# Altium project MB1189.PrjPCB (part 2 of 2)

## Sheet MCU.SchDoc: MCU
size A3; Date: 9/24/2014; Author: P.A.; CompanyName: STMicroelectronics; Organization: Microcontrollers Division; Address1: 12, Rue Jules HOROWITZ; Address2: 38019 Grenoble; Address3: FRANCE; DocumentNumber: MB1189; Revision: B-07; SheetNumber: 4; SheetTotal: 13; Project: STM32F469I-DISCO
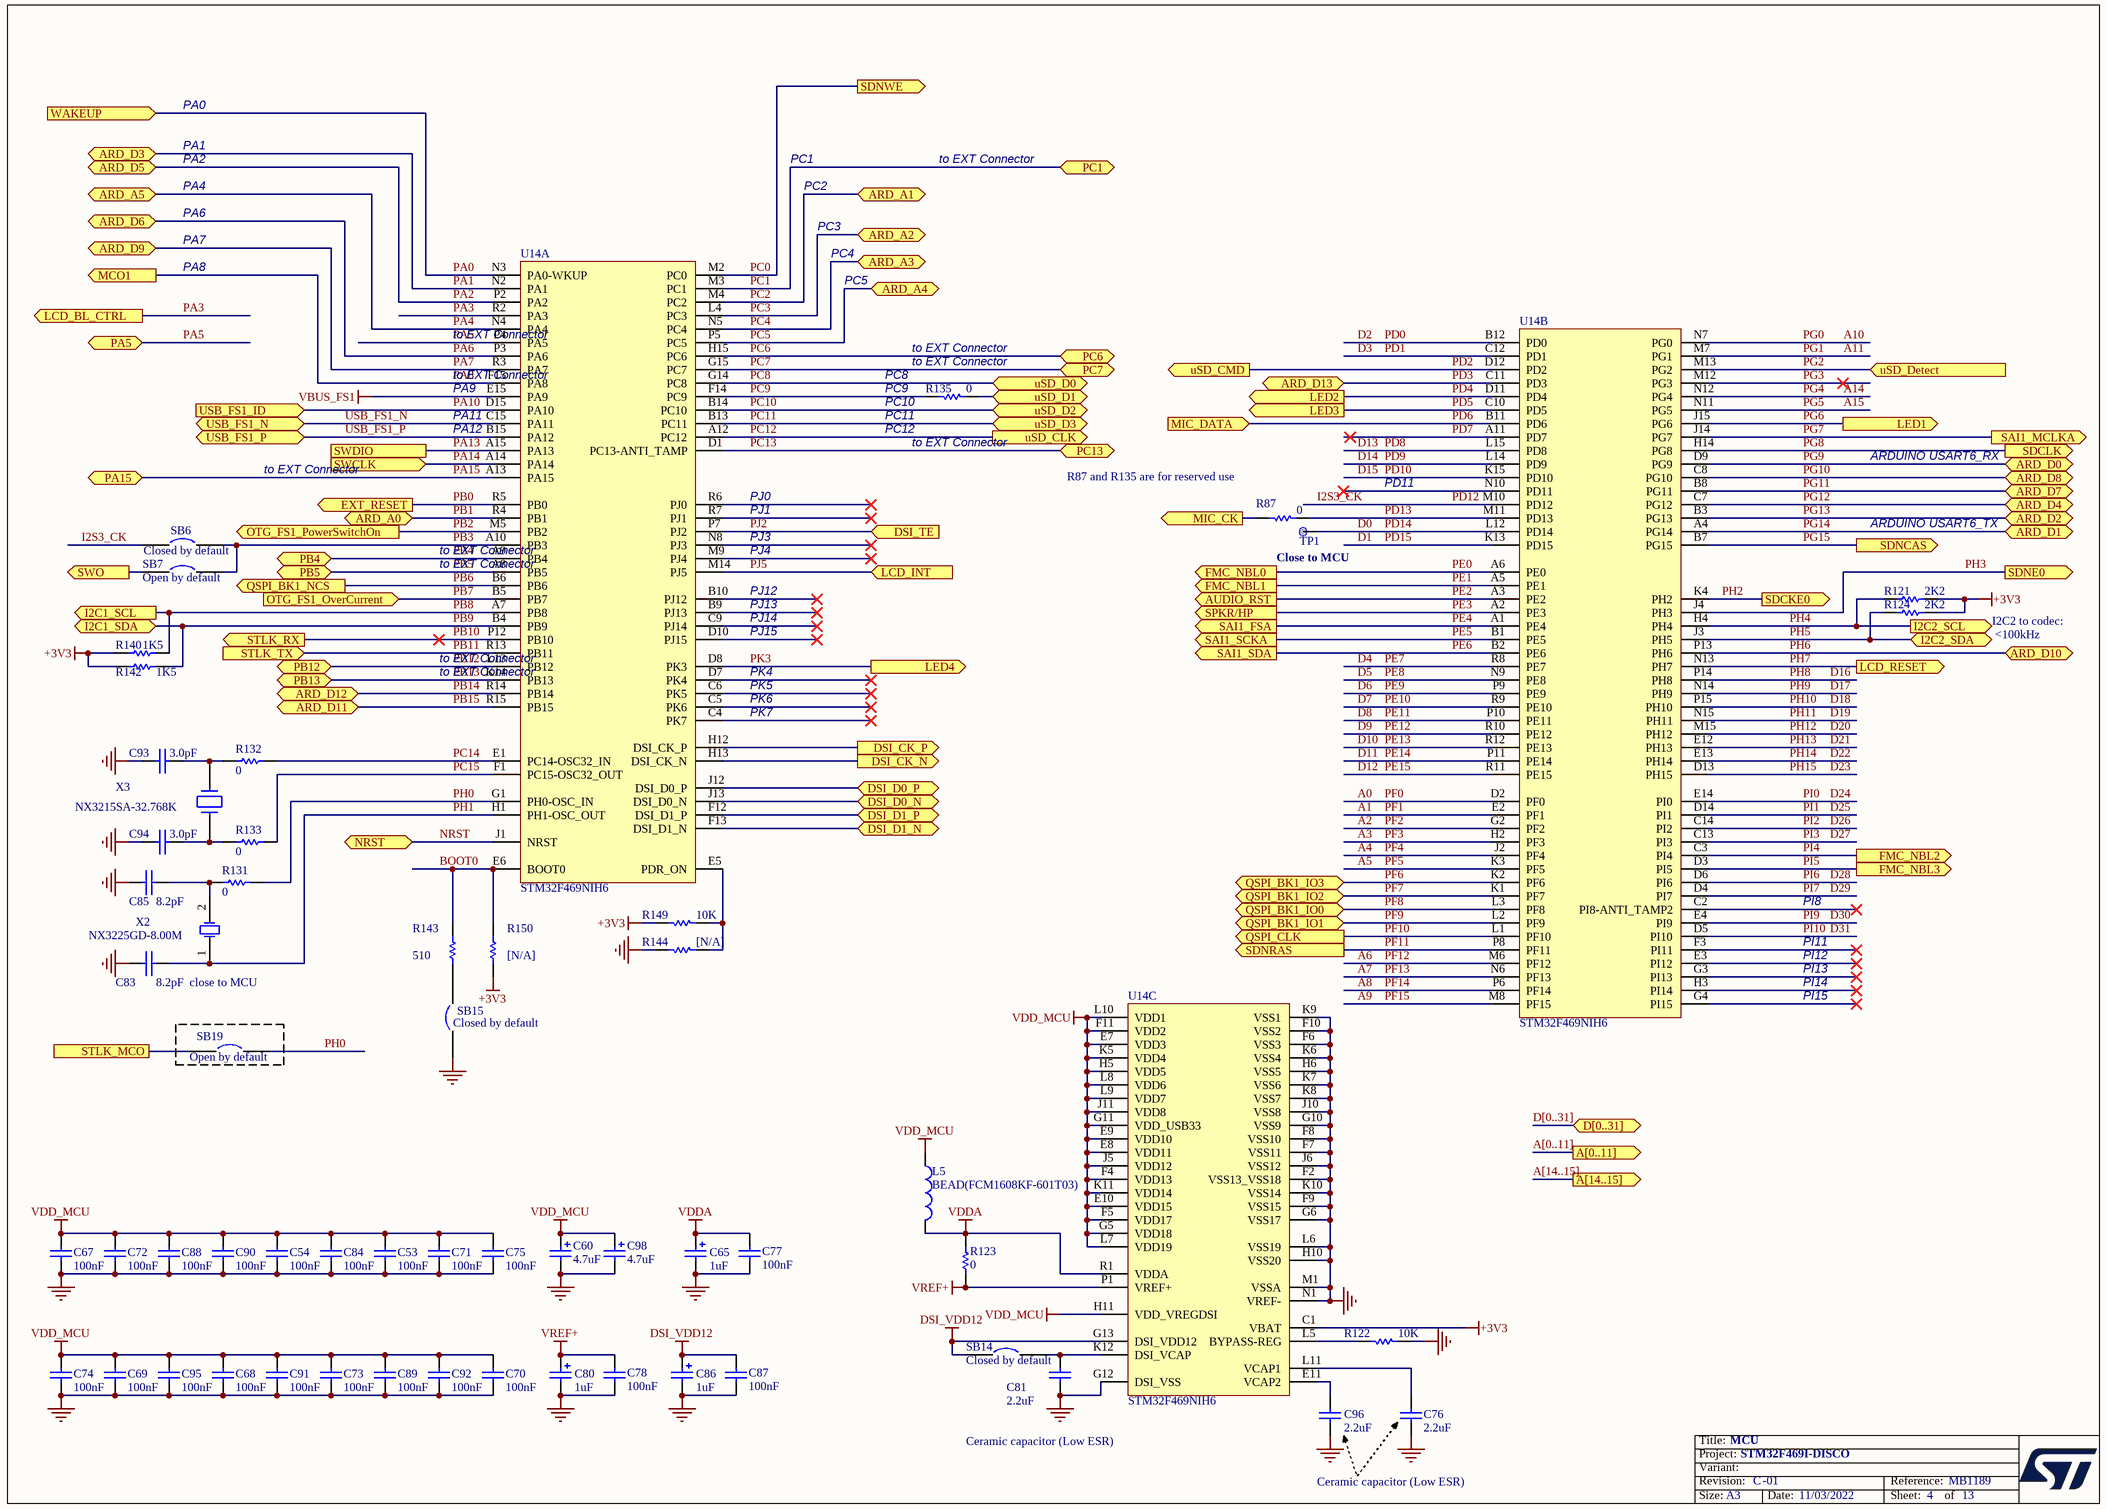
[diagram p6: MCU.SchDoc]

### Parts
C53  100nF  [0402C]
C54  100nF  [0402C]
C60  4.7uF  [CPOL_TAJ-A_1206_H180]
C65  1uF  [CPOL_TAJ-A_1206_H180]
C67  100nF  [0402C]
C68  100nF  [0402C]
C69  100nF  [0402C]
C70  100nF  [0402C]
C71  100nF  [0402C]
C72  100nF  [0402C]
C73  100nF  [0402C]
C74  100nF  [0402C]
C75  100nF  [0402C]
C76  2.2uF  [1206C]
C77  100nF  [0402C]
C78  100nF  [0402C]
C80  1uF  [CPOL_TAJ-A_1206_H180]
C81  2.2uF  [1206C]
C83  8.2pF  [0603C]
C84  100nF  [0402C]
C85  8.2pF  [0603C]
C86  1uF  [CPOL_TAJ-A_1206_H180]
C87  100nF  [0402C]
C88  100nF  [0402C]
C89  100nF  [0402C]
C90  100nF  [0402C]
C91  100nF  [0402C]
C92  100nF  [0402C]
C93  3.0pF  [0603C]
C94  3.0pF  [0603C]
C95  100nF  [0402C]
C96  2.2uF  [1206C]
C98  4.7uF  [CPOL_TAJ-A_1206_H180]
L5  BEAD(FCM1608KF-601T03)  [0603L]
R87  0  [0603R]
R121  2K2  [0603R]
R122  10K  [0402R]
R123  0  [0603R]
R124  2K2  [0603R]
R131  0  [0603R]
R132  0  [0603R]
R133  0  [0603R]
R135  0  [0603R]
R140  1K5  [0603R]
R142  1K5  [0603R]
R143  510  [0603R]
R144  [N/A]  [0603R]
R149  10K  [0402R]
R150  [N/A]  [0603R]
SB6  Closed by default  [SB_0603]
SB7  Open by default  [SB_0603]
SB14  Closed by default  [SB_0603]
SB15  Closed by default  [SB_0603]
SB19  Open by default  [SB_0603]
TP1  TP  [TP_C40]  (value not drawn)
U14  STM32F469NIH6  [BGA216_0R8_13X13]  (parts A,B,C of 3)
X2  NX3225GD-8.00M  [XTAL_2SM_3R2X2R5_H1]
X3  NX3215SA-32.768K  [XTAL_2SM_3R2X1R5]

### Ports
A[0..11] (out), A[14..15] (out), ARD_A0 (bidir), ARD_A1 (bidir), ARD_A2 (bidir), ARD_A3 (bidir), ARD_A4 (bidir), ARD_A5 (bidir), ARD_D0 (bidir), ARD_D1 (bidir), ARD_D2 (bidir), ARD_D3 (bidir), ARD_D4 (bidir), ARD_D5 (bidir), ARD_D6 (bidir), ARD_D7 (bidir), ARD_D8 (bidir), ARD_D9 (bidir), ARD_D10 (bidir), ARD_D11 (bidir), ARD_D12 (bidir), ARD_D13 (bidir), AUDIO_RST (out), D[0..31] (bidir), DSI_CK_N (out), DSI_CK_P (out), DSI_D0_N (bidir), DSI_D0_P (bidir), DSI_D1_N (bidir), DSI_D1_P (bidir), DSI_TE (in), EXT_RESET (out), FMC_NBL0 (out), FMC_NBL1 (out), FMC_NBL2 (out), FMC_NBL3 (out), I2C1_SCL (out), I2C1_SDA (bidir), I2C2_SCL (out), I2C2_SDA (bidir), LCD_BL_CTRL (out), LCD_INT (in), LCD_RESET (out), LED1 (out), LED2 (out), LED3 (out), LED4 (out), MCO1 (out), MIC_CK (out), MIC_DATA (in), NRST (bidir), OTG_FS1_OverCurrent (in), OTG_FS1_PowerSwitchOn (out), PA5 (bidir), PA15 (bidir), PB4 (bidir), PB5 (bidir), PB12 (bidir), PB13 (bidir), PC1 (bidir), PC6 (bidir), PC7 (bidir), PC13 (bidir), QSPI_BK1_IO0 (bidir), QSPI_BK1_IO1 (bidir), QSPI_BK1_IO2 (bidir), QSPI_BK1_IO3 (bidir), QSPI_BK1_NCS (out), QSPI_CLK (out), SAI1_FSA (out), SAI1_MCLKA (out), SAI1_SCKA (out), SAI1_SDA (out), SDCKE0 (out), SDCLK (out), SDNCAS (out), SDNE0 (out), SDNRAS (out), SDNWE (out), SPKR/HP (out), STLK_MCO, STLK_RX (out), STLK_TX (in), SWCLK (in), SWDIO, SWO (out), USB_FS1_ID (in), USB_FS1_N (bidir), USB_FS1_P (bidir), uSD_CLK (out), uSD_CMD (out), uSD_D0 (bidir), uSD_D1 (bidir), uSD_D2 (bidir), uSD_D3 (bidir), uSD_Detect (in), WAKEUP (in)

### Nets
+3V3: R121.1 R124.1 R140.1 R142.1 R149.2 R150.2 U14.C1(VBAT)
DSI_VDD12: C86.1 C87.2 SB14.1 U14.G13(DSI_VDD12)
GND: C53.2 C54.2 C60.2 C65.2 C67.2 C68.2 C69.2 C70.2 C71.2 C72.2 C73.2 C74.2 C75.2 C76.2 C77.1 C78.1 C80.2 C81.2 C83.2 C84.2 C85.2 C86.2 C87.1 C88.2 C89.2 C90.2 C91.2 C92.2 C93.2 C94.2 C95.2 C96.2 C98.2 R122.1 R144.2 SB15.1 U14.F2(VSS13_VSS18) U14.F6(VSS3) U14.F7(VSS11) U14.F8(VSS10) U14.F9(VSS15) U14.F10(VSS2) U14.G6(VSS17) U14.G10(VSS9) U14.G12(DSI_VSS) U14.H6(VSS5) U14.H10(VSS20) U14.J6(VSS12) U14.J10(VSS8) U14.K6(VSS4) U14.K7(VSS6) U14.K8(VSS7) U14.K9(VSS1) U14.K10(VSS14) U14.L6(VSS19) U14.M1(VSSA) U14.N1(VREF-)
VBUS_FS1: U14.E15(PA9)
VDD_MCU: C53.1 C54.1 C60.1 C67.1 C68.1 C69.1 C70.1 C71.1 C72.1 C73.1 C74.1 C75.1 C84.1 C88.1 C89.1 C90.1 C91.1 C92.1 C95.1 C98.1 L5.1 U14.E7(VDD3) U14.E8(VDD11) U14.E9(VDD10) U14.E10(VDD15) U14.F4(VDD13) U14.F5(VDD17) U14.F11(VDD2) U14.G5(VDD18) U14.G11(VDD_USB33) U14.H5(VDD5) U14.H11(VDD_VREGDSI) U14.J5(VDD12) U14.J11(VDD8) U14.K5(VDD4) U14.K11(VDD14) U14.L7(VDD19) U14.L8(VDD6) U14.L9(VDD7) U14.L10(VDD1)
VDDA: C65.1 C77.2 L5.2 R123.1 U14.R1(VDDA)
VREF+: C78.2 C80.1 R123.2 U14.P1(VREF+)
A0: U14.D2(PF0)  [also labelled PF0]
A1: U14.E2(PF1)  [also labelled PF1]
A2: U14.G2(PF2)  [also labelled PF2]
A3: U14.H2(PF3)  [also labelled PF3]
A4: U14.J2(PF4)  [also labelled PF4]
A5: U14.K3(PF5)  [also labelled PF5]
A6: U14.M6(PF12)  [also labelled PF12]
A7: U14.N6(PF13)  [also labelled PF13]
A8: U14.P6(PF14)  [also labelled PF14]
A9: U14.M8(PF15)  [also labelled PF15]
A10: U14.N7(PG0)  [also labelled PG0]
A11: U14.M7(PG1)  [also labelled PG1]
A14: U14.N12(PG4)  [also labelled PG4]
A15: U14.N11(PG5)  [also labelled PG5]
BOOT0: R143.1 R150.1 U14.E6(BOOT0)
D0: TP1.1 U14.L12(PD14)  [also labelled PD14]
D1: U14.K13(PD15)  [also labelled PD15]
D2: U14.B12(PD0)  [also labelled PD0]
D3: U14.C12(PD1)  [also labelled PD1]
D4: U14.R8(PE7)  [also labelled PE7]
D5: U14.N9(PE8)  [also labelled PE8]
D6: U14.P9(PE9)  [also labelled PE9]
D7: U14.R9(PE10)  [also labelled PE10]
D8: U14.P10(PE11)  [also labelled PE11]
D9: U14.R10(PE12)  [also labelled PE12]
D10: U14.R12(PE13)  [also labelled PE13]
D11: U14.P11(PE14)  [also labelled PE14]
D12: U14.R11(PE15)  [also labelled PE15]
D13: U14.L15(PD8)  [also labelled PD8]
D14: U14.L14(PD9)  [also labelled PD9]
D15: U14.K15(PD10)  [also labelled PD10]
D16: U14.P14(PH8)  [also labelled PH8]
D17: U14.N14(PH9)  [also labelled PH9]
D18: U14.P15(PH10)  [also labelled PH10]
D19: U14.N15(PH11)  [also labelled PH11]
D20: U14.M15(PH12)  [also labelled PH12]
D21: U14.E12(PH13)  [also labelled PH13]
D22: U14.E13(PH14)  [also labelled PH14]
D23: U14.D13(PH15)  [also labelled PH15]
D24: U14.E14(PI0)  [also labelled PI0]
D25: U14.D14(PI1)  [also labelled PI1]
D26: U14.C14(PI2)  [also labelled PI2]
D27: U14.C13(PI3)  [also labelled PI3]
D28: U14.D6(PI6)  [also labelled PI6]
D29: U14.D4(PI7)  [also labelled PI7]
D30: U14.E4(PI9)  [also labelled PI9]
D31: U14.D5(PI10)  [also labelled PI10]
HSSI_CLK_N: U14.H13(DSI_CK_N) ; port DSI_CK_N
HSSI_CLK_P: U14.H12(DSI_CK_P) ; port DSI_CK_P
HSSI_D0_N: U14.J13(DSI_D0_N) ; port DSI_D0_N
HSSI_D0_P: U14.J12(DSI_D0_P) ; port DSI_D0_P
HSSI_D1_N: U14.F13(DSI_D1_N) ; port DSI_D1_N
HSSI_D1_P: U14.F12(DSI_D1_P) ; port DSI_D1_P
I2S3_CK: SB6.1 U14.M10(PD12)  [also labelled PD12]
MIC_CK: R87.1 ; port MIC_CK
NRST: U14.J1(NRST) ; port NRST
PA0: U14.N3(PA0-WKUP) ; port WAKEUP
PA1: U14.N2(PA1) ; port ARD_D3
PA2: U14.P2(PA2) ; port ARD_D5
PA3: U14.R2(PA3) ; port LCD_BL_CTRL  [project net LCD_BL_CTRL]
PA4: U14.N4(PA4) ; port ARD_A5
PA5: U14.P4(PA5) ; port PA5
PA6: U14.P3(PA6) ; port ARD_D6
PA7: U14.R3(PA7) ; port ARD_D9
PA8: U14.F15(PA8) ; port MCO1
PA10: U14.D15(PA10) ; port USB_FS1_ID
PA13: U14.A15(PA13) ; port SWDIO
PA14: U14.A14(PA14) ; port SWCLK
PA15: U14.A13(PA15) ; port PA15
PB0: U14.R5(PB0) ; port EXT_RESET
PB1: U14.R4(PB1) ; port ARD_A0
PB2: U14.M5(PB2) ; port OTG_FS1_PowerSwitchOn
PB3: SB6.2 SB7.2 U14.A10(PB3)
PB4: U14.A9(PB4) ; port PB4
PB5: U14.A8(PB5) ; port PB5
PB6: U14.B6(PB6) ; port QSPI_BK1_NCS
PB7: U14.B5(PB7) ; port OTG_FS1_OverCurrent
PB8: R140.2 U14.A7(PB8) ; port I2C1_SCL  [project net I2C1_SCL]
PB9: R142.2 U14.B4(PB9) ; port I2C1_SDA  [project net I2C1_SDA]
PB10: U14.P12(PB10) ; port STLK_RX
PB11: U14.R13(PB11) ; port STLK_TX
PB12: U14.L13(PB12) ; port PB12
PB13: U14.K14(PB13) ; port PB13
PB14: U14.R14(PB14) ; port ARD_D12
PB15: U14.R15(PB15) ; port ARD_D11
PC0: U14.M2(PC0) ; port SDNWE
PC1: U14.M3(PC1) ; port PC1
PC2: U14.M4(PC2) ; port ARD_A1
PC3: U14.L4(PC3) ; port ARD_A2
PC4: U14.N5(PC4) ; port ARD_A3
PC5: U14.P5(PC5) ; port ARD_A4
PC6: U14.H15(PC6) ; port PC6
PC7: U14.G15(PC7) ; port PC7
PC8: U14.G14(PC8) ; port uSD_D0
PC9: R135.1 U14.F14(PC9)
PC10: U14.B14(PC10) ; port uSD_D2
PC11: U14.B13(PC11) ; port uSD_D3
PC12: U14.A12(PC12) ; port uSD_CLK
PC13: U14.D1(PC13-ANTI_TAMP) ; port PC13
PC14: R132.2 U14.E1(PC14-OSC32_IN)
PC15: R133.2 U14.F1(PC15-OSC32_OUT)
PD2: U14.D12(PD2) ; port uSD_CMD
PD3: U14.C11(PD3) ; port ARD_D13
PD4: U14.D11(PD4) ; port LED2
PD5: U14.C10(PD5) ; port LED3
PD6: U14.B11(PD6) ; port MIC_DATA
PD7: U14.A11(PD7)
PD13: R87.2 U14.M11(PD13)
PE0: U14.A6(PE0) ; port FMC_NBL0
PE1: U14.A5(PE1) ; port FMC_NBL1
PE2: U14.A3(PE2) ; port AUDIO_RST  [project net AUDIO_RST]
PE3: U14.A2(PE3) ; port SPKR/HP
PE4: U14.A1(PE4) ; port SAI1_FSA
PE5: U14.B1(PE5) ; port SAI1_SCKA
PE6: U14.B2(PE6) ; port SAI1_SDA
PF6: U14.K2(PF6) ; port QSPI_BK1_IO3
PF7: U14.K1(PF7) ; port QSPI_BK1_IO2
PF8: U14.L3(PF8) ; port QSPI_BK1_IO0
PF9: U14.L2(PF9) ; port QSPI_BK1_IO1
PF10: U14.L1(PF10) ; port QSPI_CLK
PF11: U14.P8(PF11) ; port SDNRAS
PG2: U14.M13(PG2) ; port uSD_Detect
PG3: U14.M12(PG3)
PG6: U14.J15(PG6) ; port LED1
PG7: U14.J14(PG7) ; port SAI1_MCLKA
PG8: U14.H14(PG8) ; port SDCLK
PG9: U14.D9(PG9) ; port ARD_D0
PG10: U14.C8(PG10) ; port ARD_D8
PG11: U14.B8(PG11) ; port ARD_D7
PG12: U14.C7(PG12) ; port ARD_D4
PG13: U14.B3(PG13) ; port ARD_D2
PG14: U14.A4(PG14) ; port ARD_D1
PG15: U14.B7(PG15) ; port SDNCAS
PH0: R131.1 SB19.2 U14.G1(PH0-OSC_IN)
PH1: C83.1 U14.H1(PH1-OSC_OUT) X2.1(OSC1)
PH2: U14.K4(PH2) ; port SDCKE0
PH3: U14.J4(PH3) ; port SDNE0
PH4: R121.2 U14.H4(PH4) ; port I2C2_SCL  [project net I2C2_SCL]
PH5: R124.2 U14.J3(PH5) ; port I2C2_SDA  [project net I2C2_SDA]
PH6: U14.P13(PH6) ; port ARD_D10
PH7: U14.N13(PH7) ; port LCD_RESET  [project net LCD_RST]
PI4: U14.C3(PI4) ; port FMC_NBL2
PI5: U14.D3(PI5) ; port FMC_NBL3
PJ2: U14.P7(PJ2) ; port DSI_TE
PJ5: U14.M14(PJ5) ; port LCD_INT  [project net LCD_INT]
PK3: U14.D8(PK3) ; port LED4
STLK_MCO: SB19.1 ; port STLK_MCO
SWO: SB7.1 ; port SWO
USB_FS1_N: U14.C15(PA11) ; port USB_FS1_N
USB_FS1_P: U14.B15(PA12) ; port USB_FS1_P
uSD_D1: R135.2 ; port uSD_D1
NetC76_1: C76.1 U14.L11(VCAP1)
NetC81_1: C81.1 SB14.2 U14.K12(DSI_VCAP)
NetC85_1: C85.1 R131.2 X2.2(OSC2)
NetC93_1: C93.1 R132.1 X3.1
NetC94_1: C94.1 R133.1 X3.2
NetC96_1: C96.1 U14.E11(VCAP2)
NetR122_2: R122.2 U14.L5(BYPASS-REG)
NetR143_2: R143.2 SB15.2
NetR144_1: R144.1 R149.1 U14.E5(PDR_ON)

Not connected (* = marked no-connect by the designer): U14 B9(PJ13)* B10(PJ12)* C2(PI8-ANTI_TAMP2)* C4(PK7)* C5(PK6)* C6(PK5)* C9(PJ14)* D7(PK4)* D10(PJ15)* E3(PI12)* F3(PI11)* G3(PI13)* G4(PI15)* H3(PI14)* M9(PJ4)* N8(PJ3)* N10(PD11)* R6(PJ0)* R7(PJ1)*

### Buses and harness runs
bus A[0..11] = port A[0..11]
bus A[14..15] = port A[14..15]
bus D[0..31] = port D[0..31]

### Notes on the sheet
- PA0
- PA1
- PA2
- PC1
- to EXT Connector
- PA6
- PA7
- PA4
- PC2
- PC3
- PA8
- PC4
- PC5
- (near R135) PC8
- (near R135) to EXT Connector
- (near U14) PA11
- (near U14) PA12
- (near U14) PA9
- (near R135) PC9
- (near R135) PC10
- (near R135) PC11
- (near R135) PC12
- PJ1
- PJ0
- (near R87) R87 and R135 are for reserved use
- PD11
- ARDUINO USART6_RX
- PJ4
- PJ3
- Close to MCU
- ARDUINO USART6_TX
- PJ15
- PJ13
- PJ12
- PJ14
- I2C2 to codec:
  <100kHz
- PK7
- PK6
- PK5
- PK4
- PI8
- close to MCU
- PI14
- PI13
- PI12
- PI11
- PI15
- Ceramic capacitor (Low ESR)

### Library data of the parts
C53 C67-C75 C84 C88-C92 C95 = CAP: Capacitor; Manuf_part_1: CC0402KRX7R7BB104; Manuf_1: YAGEO; Ordered by: Subcon
C54 = CAP: Capacitor; Manuf_Part_1: CC0402KRX7R7BB104; Manuf_1: YAGEO; Ordered by: Subcon
C60 C98 = Cap_TAJA475K016R: Capacitor, Tantalum, 4.7uF, 16V, 10%, 4ohms, pkg Type_A (3216 metric), T=1.6mm; Manuf_1: AVX; Value: 4.7uF 16V
C65 C80 C86 = Cap_TAJA105K016RNJ: Capacitor, Tantalum, 1uF, 16V, 10%, 11Ohms, pkg Type_A (3216 metric), T=1.6mm; Manuf_1: AVX; Value: 1uF (16V)
C76 = Cap: Capacitor; Manuf_1: YAGEO; Manuf_part_1: CC1206KKX7R7BB225; Ordered by: Subcon
C77 C78 C87 = Cap: Capacitor; Manuf_part_1: CC0402KRX7R7BB104; Manuf_1: YAGEO; Ordered by: Subcon
C81 C96 = Cap: Capacitor; Manuf_part_1: CC1206KKX7R7BB225; Manuf_1: YAGEO; Ordered by: Subcon
C83 C85 = CAP: Capacitor; Manuf_part_1: CC0603CRNPO9BN8R2; Manuf_1: YAGEO; Ordered by: Subcon
C93 C94 = CAP: Capacitor; Manuf_1: YAGEO; Manuf_part_1: CC0603CRNPO9BN3R0; Ordered by: Subcon
L5 = Inductor: Manuf_1: Tai-Tech Advanced Electronics; Manuf_part_1: FCM1608KF-601T05; Value: 100uH; Ordered by: Subcon
R87 R123 R131-R133 R135 = Res1: Resistor; Manuf_1: YAGEO; Manuf_part_1: RC0603JR-070RL; Ordered by: Subcon
R121 R124 = Res1: Resistor; Manuf_1: YAGEO; Manuf_part_1: RC0603FR-072K2L; Ordered by: Subcon
R122 R149 = Res1: Resistor; Manuf_1: YAGEO; Manuf_part_1: RC0402FR-0710KL; Ordered by: Subcon
R140 R142 = Res1: Resistor; Manuf_1: YAGEO; Manuf_part_1: RC0603FR-071K5L; Ordered by: Subcon
R143 = res1: Resistor; Manuf_1: YAGEO; Manuf_part_1: RC0603FR-07510RL; Ordered by: Subcon
R144 = Res1: Resistor; Value: 1K; Ordered by: Subcon; Fitted: NO
R150 = res1: Resistor; Value: 1K; Ordered by: Subcon; Fitted: NO
SB6 SB14 SB15 = Circuit Breaker: Ordered by: Subcon; Comments: Solder bridge
SB7 SB19 = Circuit Breaker: Ordered by: Subcon; Comments: Solder bridge; Solder: NO
TP1 = TP: Ordered by: Subcon
U14 = Manta_Dragon_TFBGA216: Manuf_Part_1: STM32F469NIH6U cut 1.0; Ordered by: ST; Ref St: 9175177; ECCN_US/EU: 3A991A2/NEC
X2 = XTAL_8M_NX3225GD: Crystal 8Mhz, 8pF, -+50PPM, SMD; Manuf_1: NDK; Manuf_Part_1: NX3225GD 8MHz EXS00A-CG04874; Manuf_Part_2: NX3225GD-8.000M-STD-CRA-3; ECCN_US/EU: EAR99/NEC; NDK Ref: X3127326; Ref St: 9157029; Provided: ST
X3 = XTAL_32K_NX3215SA: Crystal 32.768kHz, 6pF, -+20PPM, R=50K, SMD; Manuf_1: NDK; Manuf_Part_1: NX3215SA 32.768KHz EXS00A-MU00525; ECCN_US/EU: EAR99/NEC; Ref St: 9157034; NDK Ref: X3101802; Provided: ST

## Sheet Arduino_ Connectors.SchDoc: Arduino Uno connector
size A4; Date: 9/24/2014; Author: P.A.; CompanyName: STMicroelectronics; Organization: Microcontrollers Division; Address1: 12, Rue Jules HOROWITZ; Address2: 38019 Grenoble; Address3: FRANCE; DocumentNumber: MB1189; Revision: B-07; SheetNumber: 12; SheetTotal: 13; Project: STM32F469I-DISCO
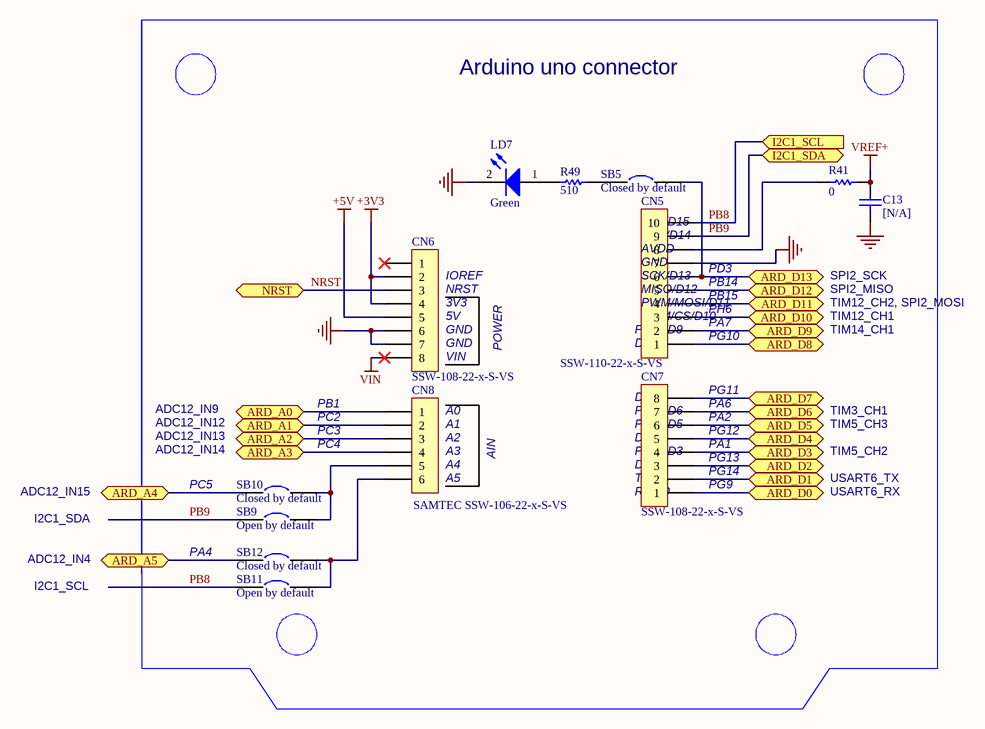
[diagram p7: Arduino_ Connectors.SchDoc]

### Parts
C13  [N/A]  [0603C]
CN5  SSW-110-22-x-S-VS  [SSW-110-22-X-S-VS]
CN6  SSW-108-22-x-S-VS  [SSW-108-22-X-S-VS]
CN7  SSW-108-22-x-S-VS  [SSW-108-22-X-S-VS]
CN8  SAMTEC SSW-106-22-x-S-VS  [SSW-106-22-X-S-VS]
LD7  Green  [0603D]
R41  0  [0603R]
R49  510  [0603R]
SB5  Closed by default  [SB_0603]
SB9  Open by default  [SB_0603]
SB10  Closed by default  [SB_0603]
SB11  Open by default  [SB_0603]
SB12  Closed by default  [SB_0603]

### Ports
ARD_A0 (bidir), ARD_A1 (bidir), ARD_A2 (bidir), ARD_A3 (bidir), ARD_A4 (bidir), ARD_A5 (bidir), ARD_D0 (bidir), ARD_D1 (bidir), ARD_D2 (bidir), ARD_D3 (bidir), ARD_D4 (bidir), ARD_D5 (bidir), ARD_D6 (bidir), ARD_D7 (bidir), ARD_D8 (bidir), ARD_D9 (bidir), ARD_D10 (bidir), ARD_D11 (bidir), ARD_D12 (bidir), ARD_D13 (bidir), I2C1_SCL (in), I2C1_SDA (bidir), NRST (bidir)

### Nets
+3V3: CN6.2 CN6.4
+5V: CN6.5
GND: C13.1 CN5.7 CN6.6 CN6.7 LD7.2(K)
VIN: CN6.8
VREF+: C13.2 R41.1
NRST: CN6.3 ; port NRST
PA1: CN7.4 ; port ARD_D3
PA2: CN7.6 ; port ARD_D5
PA4: SB12.1 ; port ARD_A5
PA6: CN7.7 ; port ARD_D6
PA7: CN5.2 ; port ARD_D9
PB1: CN8.1 ; port ARD_A0
PB8: CN5.10 SB11.1 ; port I2C1_SCL  [project net I2C1_SCL]
PB9: CN5.9 SB9.1 ; port I2C1_SDA  [project net I2C1_SDA]
PB14: CN5.5 ; port ARD_D12
PB15: CN5.4 ; port ARD_D11
PC2: CN8.2 ; port ARD_A1
PC3: CN8.3 ; port ARD_A2
PC4: CN8.4 ; port ARD_A3
PC5: SB10.1 ; port ARD_A4
PD3: CN5.6 SB5.2 ; port ARD_D13
PG9: CN7.1 ; port ARD_D0
PG10: CN5.1 ; port ARD_D8
PG11: CN7.8 ; port ARD_D7
PG12: CN7.5 ; port ARD_D4
PG13: CN7.3 ; port ARD_D2
PG14: CN7.2 ; port ARD_D1
PH6: CN5.3 ; port ARD_D10
NetCN5_8: CN5.8 R41.2
NetCN8_5: CN8.5 SB9.2 SB10.2
NetCN8_6: CN8.6 SB11.2 SB12.2
NetLD7_1: LD7.1(A) R49.2
NetR49_1: R49.1 SB5.1

Not connected (* = marked no-connect by the designer): CN6 1*

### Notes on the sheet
- Arduino uno connector
- (near CN5) SDA/D14
- SCL/D15
- (near CN5) AVDD
- (near CN6) IOREF
- (near CN6) NRST
- (near CN6) 3V3
- (near CN5) SCK/D13
- (near CN5) MISO/D12
- (near CN5) PWM/MOSI/D11
- (near CN5) GND
- (near CN5) PH6
- (near CN5) PB15
- (near CN5) PB14
- (near CN5) PD3
- TIM12_CH2, SPI2_MOSI
- SPI2_MISO
- SPI2_SCK
- (near CN6) 5V
- (near CN6) GND
- (near CN6) VIN
- POWER
- (near CN5) D8
- (near CN5) PWM/D9
- (near CN5) PWM/CS/D10
- (near CN5) PG10
- (near CN5) PA7
- TIM14_CH1
- TIM12_CH1
- ADC12_IN14
- ADC12_IN13
- ADC12_IN12
- ADC12_IN9
- PB1
- PC2
- PC3
- PC4
- (near CN8) A0
- (near CN8) A1
- (near CN8) A2
- (near CN7) D4
- (near CN7) PWM/D5
- (near CN7) PWM/D6
- (near CN7) D7
- (near CN7) PA1
- (near CN7) PG12
- (near CN7) PA2
- (near CN7) PA6
- PG11
- TIM5_CH3
- TIM3_CH1
- ADC12_IN15
- I2C1_SDA
- PC5
- (near CN8) A3
- (near CN8) A4
- (near CN8) A5
- AIN
- (near CN7) RX/D0
- (near CN7) TX/D1
- (near CN7) D2
- (near CN7) PWM/D3
- (near CN7) PG9
- (near CN7) PG14
- (near CN7) PG13
- USART6_RX
- USART6_TX
- TIM5_CH2
- ADC12_IN4
- PA4
- I2C1_SCL

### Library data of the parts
C13 = Cap: Capacitor; Value: 10nF; Ordered by: Subcon; Fitted: NO
CN5 = Header 10X1_Female: Header, 10-Pin, Single row,female; Manuf_1: SAMTEC; Ordered by: Subcon; Silkscreen: pin names as in schematic
CN6 CN7 = Header 8X1_Female: Header, 8-Pin, Single row,female; Manuf_1: SAMTEC; Ordered by: Subcon; Silkscreen: pin names as in schematic
CN8 = Header 6X1_Female: Header, 6-Pin, Single row,female SMD; Ordered by: Subcon; Silkscreen: pin names as in schematic
LD7 = LED2: Typical RED, GREEN, YELLOW, AMBER GaAs LED; Manuf_1: Everlight Electronics; Manuf_part_1: 19-217/G7C-AN1P2/3T; Ordered by: Subcon; ECCN_US/EU: EAR99/NEC
R41 = Res1: as R87 on sheet MCU
R49 = Res1: Resistor; Manuf_1: YAGEO; Manuf_part_1: RC0603FR-07510RL; Ordered by: Subcon
SB5 SB10 SB12 = Circuit Breaker: as SB6 on sheet MCU
SB9 SB11 = Circuit Breaker: as SB7 on sheet MCU

## Sheet DSI_LCD.SchDoc: 4 inch DSI LCD board
size A4; Date: 9/24/2014; Author: P.A.; CompanyName: STMicroelectronics; Organization: Microcontrollers Division; Address1: 12, Rue Jules HOROWITZ; Address2: 38019 Grenoble; Address3: FRANCE; DocumentNumber: MB1189; Revision: B-07; SheetNumber: 7; SheetTotal: 13; Project: STM32F469I-DISCO
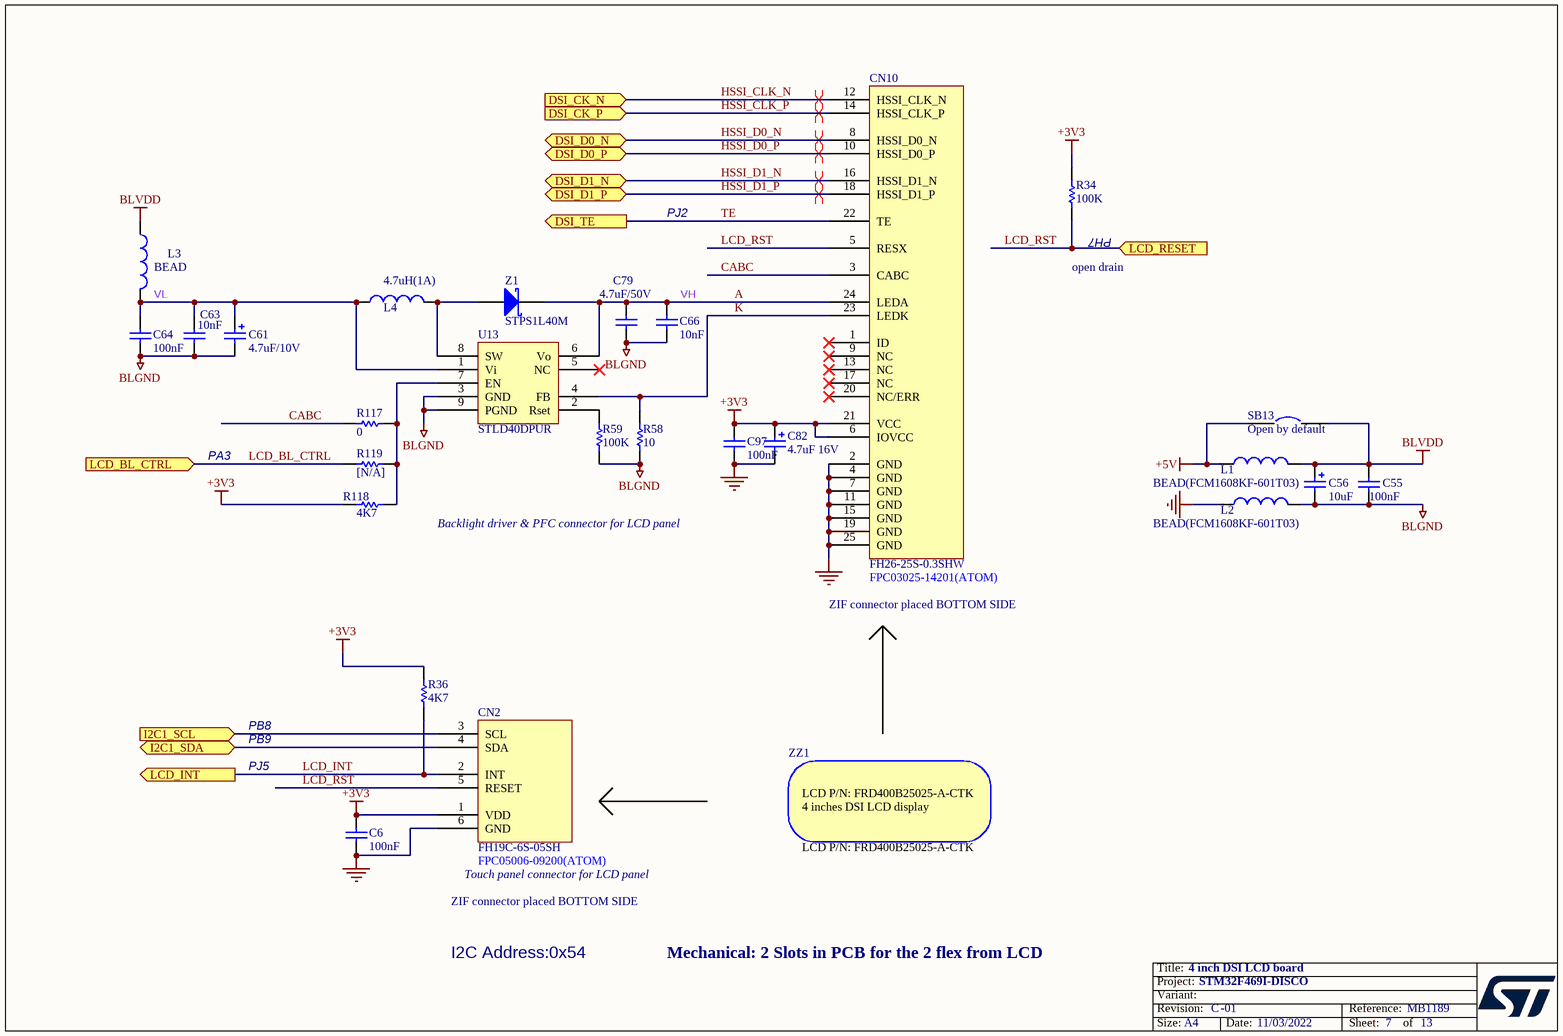
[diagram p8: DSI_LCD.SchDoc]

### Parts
C6  100nF  [0402C]
C55  100nF  [0402C]
C56  10uF  [CPOL_TAJ-A_1206_H180]
C61  4.7uF/10V  [1206C]
C63  10nF  [0603C]
C64  100nF  [0402C]
C66  10nF  [0603C]
C79  4.7uF/50V  [1206C]
C82  4.7uF 16V  [CPOL_TAJ-A_1206_H180]
C97  100nF  [0402C]
CN2  FH19C-6S-05SH  [FH19C-6S-0R5SH_FPC_CPT]
CN10  FH26-25S-0.3SHW  [FPC25_FPC03025-1420]
L1  BEAD(FCM1608KF-601T03)  [0603L]
L2  BEAD(FCM1608KF-601T03)  [0603L]
L3  BEAD  [0603L]
L4  4.7uH(1A)  [1210L]
R34  100K  [0402R]
R36  4K7  [0603R]
R58  10  [0603R]
R59  100K  [0603R]
R117  0  [0603R]
R118  4K7  [0603R]
R119  [N/A]  [0603R]
SB13  Open by default  [SB_0603]
U13  STLD40DPUR  [SON8_0R65_3X3]
Z1  STPS1L40M  [DO-216AA]
ZZ1  LCD P/N: FRD400B25025-A-CTK  [toto]  (mechanical)

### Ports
DSI_CK_N (in), DSI_CK_P (in), DSI_D0_N (bidir), DSI_D0_P (bidir), DSI_D1_N (bidir), DSI_D1_P (bidir), DSI_TE (out), I2C1_SCL (in), I2C1_SDA (bidir), LCD_BL_CTRL (in), LCD_INT (out), LCD_RESET (in)

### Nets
+3V3: C6.2 C82.1 C97.2 CN2.1(VDD) CN10.6(IOVCC) CN10.21(VCC) R34.1 R36.1 R118.2
+5V: L1.1 SB13.1
BLGND: C55.2 C56.2 C61.2 C63.1 C64.1 C66.1 C79.2 L2.2 R58.1 R59.2 U13.3(GND) U13.9(PGND)
BLVDD: C55.1 C56.1 L1.2 L3.1 SB13.2
GND: C6.1 C82.2 C97.1 CN2.6(GND) CN10.2(GND) CN10.4(GND) CN10.7(GND) CN10.11(GND) CN10.15(GND) CN10.19(GND) CN10.25(GND) L2.1
A: C66.2 C79.1 CN10.24(LEDA) U13.6(Vo) Z1.2(K)  [also labelled VH]
CABC: CN10.3(CABC) R117.2
HSSI_CLK_N: CN10.12(HSSI_CLK_N) ; port DSI_CK_N
HSSI_CLK_P: CN10.14(HSSI_CLK_P) ; port DSI_CK_P
HSSI_D0_N: CN10.8(HSSI_D0_N) ; port DSI_D0_N
HSSI_D0_P: CN10.10(HSSI_D0_P) ; port DSI_D0_P
HSSI_D1_N: CN10.16(HSSI_D1_N) ; port DSI_D1_N
HSSI_D1_P: CN10.18(HSSI_D1_P) ; port DSI_D1_P
I2C1_SCL: CN2.3(SCL) ; port I2C1_SCL
I2C1_SDA: CN2.4(SDA) ; port I2C1_SDA
K: CN10.23(LEDK) R58.2 U13.4(FB)
LCD_BL_CTRL: R119.2 ; port LCD_BL_CTRL
LCD_INT: CN2.2(INT) R36.2 ; port LCD_INT
LCD_RST: CN2.5(RESET) CN10.5(RESX) R34.2 ; port LCD_RESET
TE: CN10.22(TE) ; port DSI_TE  [project net PJ2]
VL: C61.1 C63.2 C64.2 L3.2 L4.1 U13.1(Vi)
NetL4_2: L4.2 U13.8(SW) Z1.1(A)
NetR59_1: R59.1 U13.2(Rset)
NetR117_1: R117.1 R118.1 R119.1 U13.7(EN)

Not connected (* = marked no-connect by the designer): CN10 1(ID)* 9(NC)* 13(NC)* 17(NC)* 20(NC/ERR)*; U13 5(NC)*

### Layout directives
differential pair: HSSI_CLK_N, HSSI_CLK_P, HSSI_D0_N, HSSI_D0_P, HSSI_D1_N, HSSI_D1_P

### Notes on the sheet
- PJ2
- (near R34) PH7
- open drain
- PA3
- Backlight driver & PFC connector for LCD panel
- (near CN10) FPC03025-14201(ATOM)
- ZIF connector placed BOTTOM SIDE
- PB9
- PB8
- PJ5
- (near CN2) Touch panel connector for LCD panel
- (near CN2) FPC05006-09200(ATOM)
- I2C Address:0x54
- Mechanical: 2 Slots in PCB for the 2 flex from LCD

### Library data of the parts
C6 C64 C97 = CAP: as C53 on sheet MCU
C55 = Cap: as C77 on sheet MCU
C56 = Cap_TAJA106K016R: Capacitor, Tantalum, 10uF, 16V, 10%, 3Ohms, pkg Type_A (3216 metric), T=1.6mm; Manuf_1: AVX; Value: 10uF (16V)
C61 = Cap Pol1: Polarized Capacitor (Radial); Manuf_part_1: CC1206KKX7R8BB475; Manuf_1: YAGEO; Value: 4.7uF; Ordered by: Subcon
C63 C66 = CAP: Capacitor; Manuf_part_1: CC0603KRX7R9BB103; Manuf_1: YAGEO; Ordered by: Subcon
C79 = CAP: Capacitor; Manuf_part_1: CC1206KKX7R9BB475; Manuf_1: YAGEO; Value: 4.7uF; Ordered by: Subcon
C82 = Cap_TAJA475K016R: Capacitor, Tantalum, 4.7uF, 16V, 10%, 4ohms, pkg Type_A (3216 metric), T=1.6mm; Manuf_1: AVX
CN2 = FH19C-6S-05SH: ZIF connector placed bottom side; Manuf_1: ATOM; Manuf_2: Hirose; Manuf_Part_1: FPC05006-09200; Ordered by: Subcon; Silkscreen: TS
CN10 = FH26-25S-0.3SHW: ZIF connector placed bottom side; Manuf_1: ATOM; Manuf_Part_1: FPC03025-14201; Manuf_2: Hirose; Ordered by: Subcon; Comments: Hirose FH26-25S-0.3SHW; Silkscreen: DSI LCD
L1-L3 = Inductor: as L5 on sheet MCU
L4 = Inductor: Manuf_part_1: LQH32PN4R7NN0L; Manuf_1: Murata Manufacturing; Ordered by: Subcon
R34 = Res1: Resistor; Manuf_part_1: RC0402FR-07100KL; Manuf_1: YAGEO; Ordered by: Subcon
R36 R118 = Res1: Resistor; Manuf_1: YAGEO; Manuf_part_1: RC0603FR-074K7L; Ordered by: Subcon
R58 = Res1: Resistor; Manuf_1: YAGEO; Manuf_part_1: RC0603FR-0710RL; Ordered by: Subcon
R59 = Res1: Resistor; Manuf_1: YAGEO; Manuf_part_1: RC0603FR-07100KL; Ordered by: Subcon
R117 = Res1: as R87 on sheet MCU
R119 = Res1: as R144 on sheet MCU
SB13 = Circuit Breaker: as SB7 on sheet MCU
U13 = STLD40DPMR: Ordered by: ST; Ref St: 9176009; ECCN_US/EU: EAR99/NEC
Z1 = D Schottky: Schottky Diode; Code - JEDEC: DO-214-AA; Ordered by: ST; Ref St: 9151085; ECCN_US/EU: EAR99/NEC
ZZ1 = LCD: 4 inches DSI LCD with touch screen; Manuf_1: Techshine; Manuf_Part_1: TS-P0400022A; Ordered by: Subcon; Comments: 4 inches DSI LCD display; ECCN_US/EU: EAR99/NEC; Value: TS-P0400022A

## Sheet QSPI.SchDoc: QSPI
size A4; Date: 9/24/2014; Author: P.A.; CompanyName: STMicroelectronics; Organization: Microcontrollers Division; Address1: 12, Rue Jules HOROWITZ; Address2: 38019 Grenoble; Address3: FRANCE; DocumentNumber: MB1189; Revision: B-07; SheetNumber: 6; SheetTotal: 13; Project: STM32F469I-DISCO
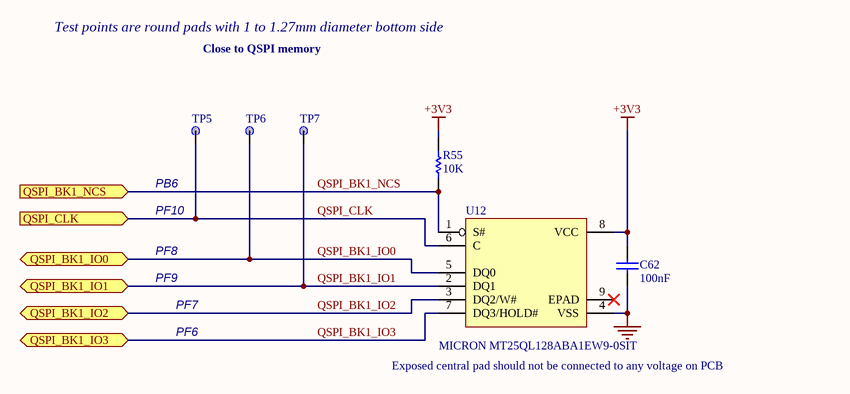
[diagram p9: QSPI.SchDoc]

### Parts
C62  100nF  [0402C]
R55  10K  [0402R]
TP5  TP  [TP_C40]  (value not drawn)
TP6  TP  [TP_C40]  (value not drawn)
TP7  TP  [TP_C40]  (value not drawn)
U12  MICRON MT25QL128ABA1EW9-0SIT  [ICC_W-PDFN-8_8X6_P127]

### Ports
QSPI_BK1_IO0 (bidir), QSPI_BK1_IO1 (bidir), QSPI_BK1_IO2 (bidir), QSPI_BK1_IO3 (bidir), QSPI_BK1_NCS (in), QSPI_CLK (in)

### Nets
+3V3: C62.1 R55.2 U12.8(VCC)
GND: C62.2 U12.4(VSS)
QSPI_BK1_IO0: TP6.1 U12.5(DQ0) ; port QSPI_BK1_IO0  [project net PF8]
QSPI_BK1_IO1: TP7.1 U12.2(DQ1) ; port QSPI_BK1_IO1  [project net PF9]
QSPI_BK1_IO2: U12.3(DQ2/W#) ; port QSPI_BK1_IO2  [project net PF7]
QSPI_BK1_IO3: U12.7(DQ3/HOLD#) ; port QSPI_BK1_IO3  [project net PF6]
QSPI_BK1_NCS: R55.1 U12.1(S#) ; port QSPI_BK1_NCS  [project net PB6]
QSPI_CLK: TP5.1 U12.6(C) ; port QSPI_CLK  [project net PF10]

Not connected (* = marked no-connect by the designer): U12 9(EPAD)*

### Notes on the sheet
- Test points are round pads with 1 to 1.27mm diameter bottom side
- Close to QSPI memory
- (near TP5) PB6
- PF10
- PF8
- PF9
- PF7
- PF6
- (near U12) Exposed central pad should not be connected to any voltage on PCB

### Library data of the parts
C62 = Cap: as C77 on sheet MCU
R55 = Res_10K_1%_0402: Resistor; Manuf_Part_1: RC0402FR-0710KL; Manuf_1: YAGEO; Ordered by: Subcon
TP5-TP7 = TP: Ordered by: Subcon
U12 = MT25QL128ABA1EW9-0SIT: 128Mb, 3V, Multiple I/O Serial Flash Memory, Quad/Dual; ECCN_US/EU: 3A991/NEC; Ref St: 9171975

## Sheet AUDIO2.SchDoc: Audio Codec and Microphone MEMS
size A4; Date: 9/24/2014; Author: P.A.; CompanyName: STMicroelectronics; Organization: Microcontrollers Division; Address1: 12, Rue Jules HOROWITZ; Address2: 38019 Grenoble; Address3: FRANCE; DocumentNumber: MB1189; Revision: B-07; SheetNumber: 9; SheetTotal: 13; Project: STM32F469I-DISCO
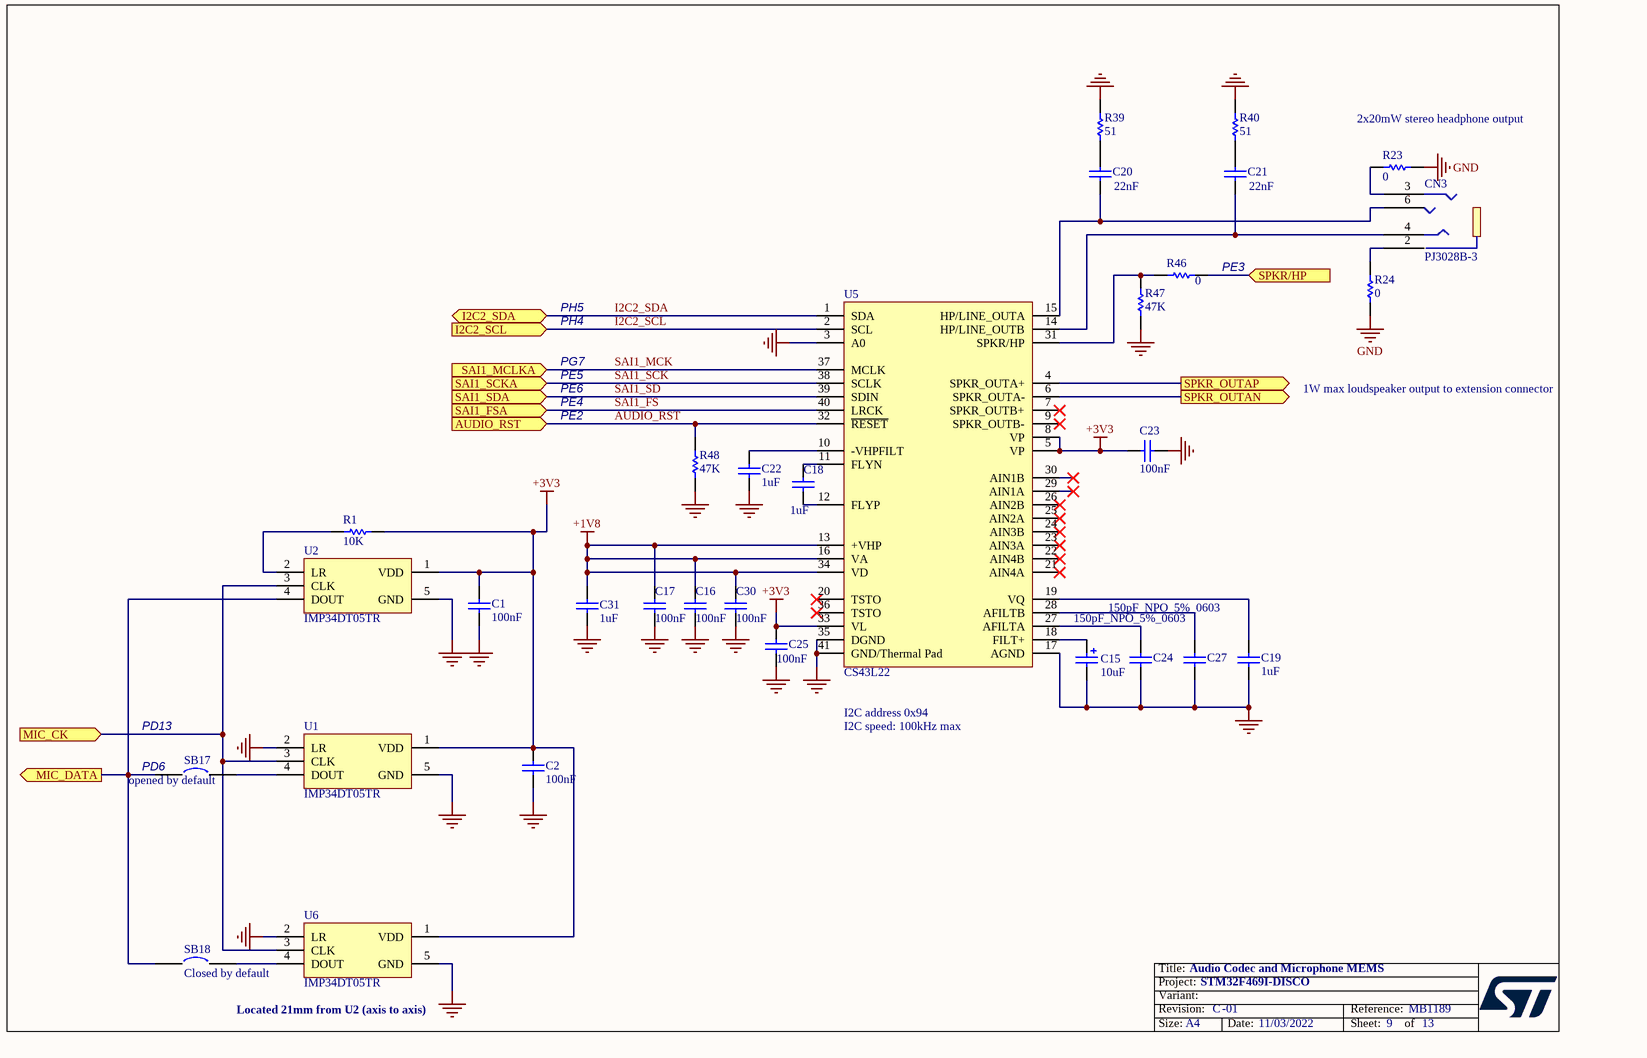
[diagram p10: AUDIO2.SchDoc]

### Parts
C1  100nF  [0402C]
C2  100nF  [0402C]
C15  10uF  [CPOL_TAJ-A_1206_H180]
C16  100nF  [0402C]
C17  100nF  [0402C]
C18  1uF  [0603C]
C19  1uF  [0603C]
C20  22nF  [0603C]
C21  22nF  [0603C]
C22  1uF  [0603C]
C23  100nF  [0402C]
C24  150pF_NPO_5%_0603  [0603C]
C25  100nF  [0402C]
C27  150pF_NPO_5%_0603  [0603C]
C30  100nF  [0402C]
C31  1uF  [0603C]
CN3  PJ3028B-3  [PJ3028B]
R1  10K  [0603R]
R23  0  [0603R]
R24  0  [0603R]
R39  51  [0402R]
R40  51  [0402R]
R46  0  [0603R]
R47  47K  [0603R]
R48  47K  [0603R]
SB17  opened by default  [SB_0603]
SB18  Closed by default  [SB_0603]
U1  IMP34DT05TR  [MIC_HCLGA_3X4X1_4LD_]
U2  IMP34DT05TR  [MIC_HCLGA_3X4X1_4LD_]
U5  CS43L22  [QFN40_0R5_6X6]
U6  IMP34DT05TR  [MIC_HCLGA_3X4X1_4LD_]

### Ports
AUDIO_RST (in), I2C2_SCL (in), I2C2_SDA (bidir), MIC_CK (in), MIC_DATA (out), SAI1_FSA (in), SAI1_MCLKA (in), SAI1_SCKA (in), SAI1_SDA (in), SPKR/HP (in), SPKR_OUTAN (out), SPKR_OUTAP (out)

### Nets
+1V8: C16.1 C17.1 C30.1 C31.1 U5.13(+VHP) U5.16(VA) U5.34(VD)
+3V3: C1.2 C2.2 C23.2 C25.1 R1.2 U1.1(VDD) U2.1(VDD) U5.5(VP) U5.8(VP) U5.33(VL) U6.1(VDD)
GND: C1.1 C2.1 C15.2 C16.2 C17.2 C19.1 C22.1 C23.1 C24.1 C25.2 C27.1 C30.2 C31.2 R23.2 R24.2 R39.2 R40.2 R47.2 R48.1 U1.2(LR) U1.5(GND) U2.5(GND) U5.3(A0) U5.17(AGND) U5.35(DGND) U5.41(GND/Thermal_Pad) U6.2(LR) U6.5(GND)
AUDIO_RST: R48.2 U5.32(~{RESET}) ; port AUDIO_RST
I2C2_SCL: U5.2(SCL) ; port I2C2_SCL
I2C2_SDA: U5.1(SDA) ; port I2C2_SDA
MIC_CK: U1.3(CLK) U2.3(CLK) U6.3(CLK) ; port MIC_CK
PD6: SB17.2 SB18.2 U2.4(DOUT) ; port MIC_DATA
PE3: R46.2 ; port SPKR/HP
SAI1_FS: U5.40(LRCK) ; port SAI1_FSA  [project net PE4]
SAI1_MCK: U5.37(MCLK) ; port SAI1_MCLKA  [project net PG7]
SAI1_SCK: U5.38(SCLK) ; port SAI1_SCKA  [project net PE5]
SAI1_SD: U5.39(SDIN) ; port SAI1_SDA  [project net PE6]
SPKR_OUTAN: U5.6(SPKR_OUTA-) ; port SPKR_OUTAN
SPKR_OUTAP: U5.4(SPKR_OUTA+) ; port SPKR_OUTAP
NetC15_1: C15.1 U5.18(FILT+)
NetC18_1: C18.1 U5.11(FLYN)
NetC18_2: C18.2 U5.12(FLYP)
NetC19_2: C19.2 U5.19(VQ)
NetC20_1: C20.1 CN3.6 U5.15(HP/LINE_OUTA)
NetC20_2: C20.2 R39.1
NetC21_1: C21.1 CN3.4 U5.14(HP/LINE_OUTB)
NetC21_2: C21.2 R40.1
NetC22_2: C22.2 U5.10(-VHPFILT)
NetC24_2: C24.2 U5.27(AFILTA)
NetC27_2: C27.2 U5.28(AFILTB)
NetCN3_2: CN3.2 R24.1
NetCN3_3: CN3.3 R23.1
NetR1_1: R1.1 U2.2(LR)
NetR46_1: R46.1 R47.1 U5.31(SPKR/HP)
NetSB17_1: SB17.1 U1.4(DOUT)
NetSB18_1: SB18.1 U6.4(DOUT)

Not connected (* = marked no-connect by the designer): U5 7(SPKR_OUTB+)* 9(SPKR_OUTB-)* 20(TSTO)* 21(AIN4A)* 22(AIN4B)* 23(AIN3A)* 24(AIN3B)* 25(AIN2A)* 26(AIN2B)* 29(AIN1A)* 30(AIN1B)* 36(TSTO)*

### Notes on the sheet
- (near R23) 2x20mW stereo headphone output
- PH5
- (near R46) PE3
- PE5
- PG7
- PH4
- PE6
- PE4
- PE2
- 1W max loudspeaker output to extension connector
- I2C address 0x94
- (near SB17) PD13
- (near SB17) PD6
- I2C speed: 100kHz max
- Located 21mm from U2 (axis to axis)

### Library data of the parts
C1 C2 = Cap: as C77 on sheet MCU
C15 = Cap_TAJA106K016R: as C56 on sheet DSI_LCD
C16 C23 C25 C30 = CAP: as C53 on sheet MCU
C17 = CAP: as C54 on sheet MCU
C18 C22 C31 = CAP: Capacitor; Manuf_part_1: CC0603KRX5R7BB105; Manuf_1: YAGEO; Ordered by: Subcon
C19 = CAP: Capacitor; Manuf_1: YAGEO; Manuf_part_1: CC0603KRX5R7BB105; Ordered by: Subcon
C20 C21 = Cap_22nF_X7R_10%_0603: Capacitor,22nF,50V,X7R,10%,0603,YAGEO; Manuf_Part_1: CC0603KRX7R9BB223; Ordered by: Subcon
C24 C27 = Cap_150pF_NPO_5%_0603: Capacitor,150pF,50V,NPO,5%,0603,YAGEO; Order: CC0603JRNPO9BN151; Ordered by: Subcon
CN3 = PJ3028B-3: Manuf_1: QIAOD; Ordered by: Subcon; Silkscreen: AUDIO JACK
R1 = Res_0_5%_0402: Resistor; Manuf_Part_1: RC0603FR-0710KL; Manuf_1: YAGEO; Order: 2363467; Ordered by: Subcon
R23 R24 R46 = Res1: as R87 on sheet MCU
R39 R40 = Res_51_1%_0402: Resistor; Manuf_Part_1: RC0402FR-0751RL; Manuf_1: YAGEO; Order: 311-51.0LRTR-ND; Ordered by: Subcon
R47 R48 = Res1: Resistor; Manuf_1: YAGEO; Manuf_part_1: RC0603FR-0747KL; Ordered by: Subcon
SB17 = Circuit Breaker: Ordered by: Subcon; Comments: Solder bridge; solder: NO
SB18 = Circuit Breaker: as SB6 on sheet MCU
U1 U2 U6 = IMP34DT05TR: MEMS audio sensor omnidirectional digital microphone for industrial applications; Ordered by: ST; Ref St: 9177995; ECCN_US/EU: EAR99/NEC
U5 = CS43L22: Low Power, Stereo DAC w/Headphone & Speaker Amps; Manuf_1: Cirrus; Order: CS43L22-CNZ; ECCN_US/EU: EAR99/NEC; Ordered by: Subcon

## Sheet USB_OTG_FS.SchDoc: USB_OTG_FS
size A4; Date: 9/24/2014; Author: P.A.; CompanyName: STMicroelectronics; Organization: Microcontrollers Division; Address1: 12, Rue Jules HOROWITZ; Address2: 38019 Grenoble; Address3: FRANCE; DocumentNumber: MB1189; Revision: B-07; SheetNumber: 8; SheetTotal: 13; Project: STM32F469I-DISCO
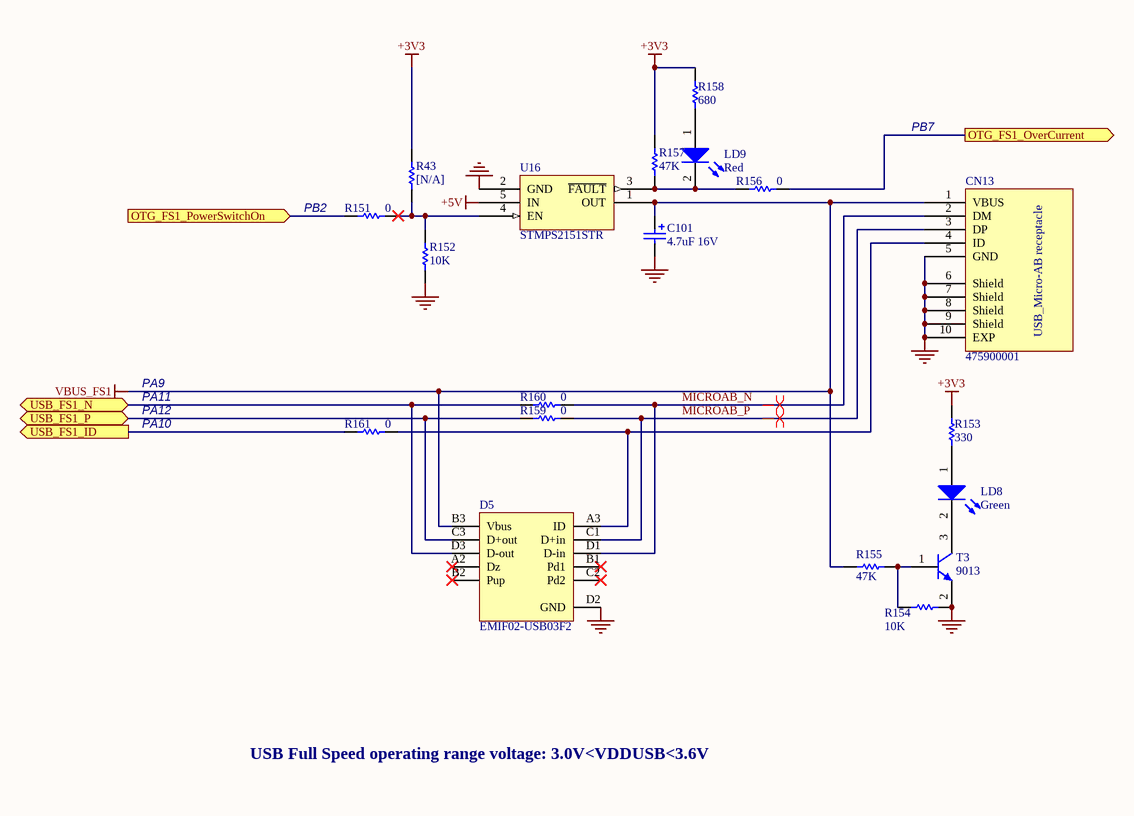
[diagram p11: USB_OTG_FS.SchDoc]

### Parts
C101  4.7uF 16V  [CPOL_TAJ-A_1206_H180]
CN13  475900001  [MOLEX_47590001]
D5  EMIF02-USB03F2  [BGA11_0R5_1R57X2R07]
LD8  Green  [0603D]
LD9  Red  [0603D]
R43  [N/A]  [0603R]
R151  0  [0603R]
R152  10K  [0402R]
R153  330  [0603R]
R154  10K  [0603R]
R155  47K  [0603R]
R156  0  [0603R]
R157  47K  [0603R]
R158  680  [0603R]
R159  0  [0603R]
R160  0  [0603R]
R161  0  [0603R]
T3  9013  [SOT-23]
U16  STMPS2151STR  [SOT23-5]

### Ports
OTG_FS1_OverCurrent (out), OTG_FS1_PowerSwitchOn (in), USB_FS1_ID (out), USB_FS1_N (bidir), USB_FS1_P (bidir)

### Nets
+3V3: R43.1 R153.2 R157.1 R158.2
+5V: U16.5(IN)
GND: C101.2 CN13.5(GND) CN13.6(Shield) CN13.7(Shield) CN13.8(Shield) CN13.9(Shield) CN13.10(EXP) D5.D2(GND) R152.1 R154.1 T3.2(E) U16.2(GND)
VBUS_FS1: C101.1 CN13.1(VBUS) D5.B3(Vbus) R155.1 U16.1(OUT)
MICROAB_N: CN13.2(DM) D5.D1(D-in) R160.1
MICROAB_P: CN13.3(DP) D5.C1(D+in) R159.1
PA10: R161.2 ; port USB_FS1_ID
PB2: R151.2 ; port OTG_FS1_PowerSwitchOn
PB7: R156.1 ; port OTG_FS1_OverCurrent
USB_FS1_N: D5.D3(D-out) R160.2 ; port USB_FS1_N
USB_FS1_P: D5.C3(D+out) R159.2 ; port USB_FS1_P
NetCN13_4: CN13.4(ID) D5.A3(ID) R161.1
NetLD8_1: LD8.1(A) R153.1
NetLD8_2: LD8.2(K) T3.3(C)
NetLD9_1: LD9.1(A) R158.1
NetLD9_2: LD9.2(K) R156.2 R157.2 U16.3(~{FAULT})
NetR43_2: R43.2 R151.1 R152.2 U16.4(EN)
NetR154_2: R154.2 R155.2 T3.1(B)

Not connected (* = marked no-connect by the designer): D5 A2(Dz)* B1(Pd1)* B2(Pup)* C2(Pd2)*

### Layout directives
differential pair: MICROAB_N, MICROAB_P

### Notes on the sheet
- PB7
- (near R151) PB2
- PA9
- PA10
- PA11
- PA12
- USB Full Speed operating range voltage: 3.0V<VDDUSB<3.6V

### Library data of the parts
C101 = Cap_TAJA475K016R: as C82 on sheet DSI_LCD
CN13 = 475900001: Manuf_1: MOLEX; Ordered by: Subcon; Silkscreen: USB USER
D5 = EMIF02-USB03F2: 2-line IPAD, EMI filter including ESD protection; Manuf_1: ST; ECCN_US/EU: EAR99/NEC; Ref St: 9179037
LD8 = LED2: Typical RED, GREEN, YELLOW, AMBER GaAs LED; Manuf_1: Everlight Electronics; Manuf_part_1: 19-217/G7C-AN1P2/3T; Ordered by: Subcon; ECCN_US/EU: EAR99/NEC; Silkscreen: VBUS
LD9 = LED2: Typical RED, GREEN, YELLOW, AMBER GaAs LED; Manuf_1: Everlight Electronics; Manuf_part_1: 19-217/R6C-AL1M2VY/3T; Ordered by: Subcon; ECCN_US/EU: EAR99/NEC; Silkscreen: FAULT
R43 = Res1: as R144 on sheet MCU
R151 R156 R159 R161 = Res1: as R87 on sheet MCU
R152 = Res1: as R122 on sheet MCU
R153 = res1: Resistor; Manuf_part_1: RC0603FR-07330RL; Manuf_1: YAGEO; Ordered by: Subcon
R154 = res1: Resistor; Manuf_1: YAGEO; Manuf_part_1: RC0603FR-0710KL; Ordered by: Subcon
R155 R157 = res1: Resistor; Manuf_1: YAGEO; Manuf_part_1: RC0603FR-0747KL; Ordered by: Subcon
R158 = Res1: Resistor; Manuf_1: YAGEO; Manuf_part_1: RC0603FR-07680RL; Ordered by: Subcon
R160 = Res1: Resistor; Manuf_1: YAGEO; Manuf_Part_1: RC0603JR-070RL; Ordered by: Subcon
T3 = NPN: NPN Bipolar Transistor; Manuf_Part_1: MMBT9013; Code - JEDEC: TO-226-AA; Ordered by: Subcon; ECCN_US/EU: EAR99/NEC
U16 = STMPS2141STR: Ordered by: ST; Ref St: 9159009; ECCN_US/EU: EAR99/NEC

## Sheet ExtensionConnector.SchDoc: Extension Connectors
size A4; Date: 9/24/2014; Author: P.A.; CompanyName: STMicroelectronics; Organization: Microcontrollers Division; Address1: 12, Rue Jules HOROWITZ; Address2: 38019 Grenoble; Address3: FRANCE; DocumentNumber: MB1189; Revision: B-07; SheetNumber: 13; SheetTotal: 13; Project: STM32F469I-DISCO
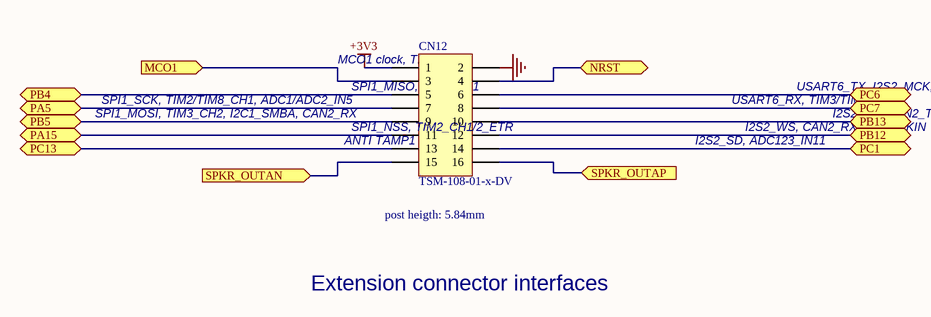
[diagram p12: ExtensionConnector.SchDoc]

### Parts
CN12  TSM-108-01-x-DV  [TSM-108-01-X-DV]

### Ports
MCO1 (in), NRST (bidir), PA5 (bidir), PA15 (bidir), PB4 (bidir), PB5 (bidir), PB12 (bidir), PB13 (bidir), PC1 (bidir), PC6 (bidir), PC7 (bidir), PC13 (bidir), SPKR_OUTAN (in), SPKR_OUTAP (in)

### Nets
+3V3: CN12.1
GND: CN12.2
NRST: CN12.4 ; port NRST
PA5: CN12.7 ; port PA5
PA8: CN12.3 ; port MCO1
PA15: CN12.11 ; port PA15
PB4: CN12.5 ; port PB4
PB5: CN12.9 ; port PB5
PB12: CN12.12 ; port PB12
PB13: CN12.10 ; port PB13
PC1: CN12.14 ; port PC1
PC6: CN12.6 ; port PC6
PC7: CN12.8 ; port PC7
PC13: CN12.13 ; port PC13
SPKR_OUTAN: CN12.15 ; port SPKR_OUTAN
SPKR_OUTAP: CN12.16 ; port SPKR_OUTAP

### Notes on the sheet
- MCO1 clock, TIM1_CH1
- SPI1_MISO, TIM3_CH1
- USART6_TX, I2S2_MCK, TIM3/TIM8_CH1
- SPI1_MOSI, TIM3_CH2, I2C1_SMBA, CAN2_RX
- SPI1_SCK, TIM2/TIM8_CH1, ADC1/ADC2_IN5
- ANTI TAMP1
- SPI1_NSS, TIM2_CH1/2_ETR
- I2S2_SD, ADC123_IN11
- USART6_RX, TIM3/TIM8_CH2
- I2S2_WS, CAN2_RX, TIM1_BKIN
- I2S2_CK, CAN2_TX, USART3_CTS, TIM1_CH1N
- (near CN12) post heigth: 5.84mm
- Extension connector interfaces

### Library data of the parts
CN12 = Header 8X2: Header, 8-Pin, Dual row; Manuf_1: SAMTEC; Ordered by: Subcon; Silkscreen: EXT

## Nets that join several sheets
+1V8: Power (C32.1 U8.2 U8.4), AUDIO2 (7 pins)
+3V3: Memory (28 pins), Peripherals (15 pins), Power (C41.1 JP5.1 SB8.2 U8.3), ST_LINK_V2-1 (R33.1), MCU (7 pins), Arduino_ Connectors (CN6.2 CN6.4), DSI_LCD (9 pins), QSPI (C62.1 R55.2 U12.8), AUDIO2 (11 pins), USB_OTG_FS (R43.1 R153.2 R157.1 R158.2), ExtensionConnector (CN12.1)
+5V: Power (6 pins), ST_LINK_V2-1 (D1.1), Arduino_ Connectors (CN6.5), DSI_LCD (L1.1 SB13.1), USB_OTG_FS (U16.5)
E5V: Power (C35.1 JP2.1 U10.2 U10.4), ST_LINK_V2-1 (D2.1)
GND: Top (H1.1 H2.1 H3.1 H4.1), Memory (28 pins), Peripherals (7 pins), Power (12 pins), ST_LINK_V2-1 (34 pins), MCU (57 pins), Arduino_ Connectors (5 pins), DSI_LCD (12 pins), QSPI (C62.2 U12.4), AUDIO2 (28 pins), USB_OTG_FS (12 pins), ExtensionConnector (CN12.2)
U5V_ST_LINK: Power (JP2.3), ST_LINK_V2-1 (C14.2 U4.6 U4.7)
VBUS_FS1: Power (JP2.5), ST_LINK_V2-1 (D3.1), MCU (U14.E15), USB_OTG_FS (5 pins)
VDD_MCU: Power (JP5.2), MCU (40 pins)
VIN: Power (C36.1 U10.3), Arduino_ Connectors (CN6.8)
VREF+: MCU (C78.2 C80.1 R123.2 U14.P1), Arduino_ Connectors (C13.2 R41.1)
A0: Memory (U11.G8), MCU (U14.D2)
A1: Memory (U11.G9), MCU (U14.E2)
A2: Memory (U11.F7), MCU (U14.G2)
A3: Memory (U11.F3), MCU (U14.H2)
A4: Memory (U11.G1), MCU (U14.J2)
A5: Memory (U11.G2), MCU (U14.K3)
A6: Memory (U11.G3), MCU (U14.M6)
A7: Memory (U11.H1), MCU (U14.N6)
A8: Memory (U11.H2), MCU (U14.P6)
A9: Memory (U11.J3), MCU (U14.M8)
A10: Memory (U11.G7), MCU (U14.N7)
A11: Memory (U11.H9), MCU (U14.M7)
A14: Memory (U11.J7), MCU (U14.N12)
A15: Memory (U11.H8), MCU (U14.N11)
AUDIO_RST: MCU (U14.A3), AUDIO2 (R48.2 U5.32)
D0: Memory (TP4.1 U11.R8), MCU (TP1.1 U14.L12)
D1: Memory (U11.N7), MCU (U14.K13)
D2: Memory (U11.R9), MCU (U14.B12)
D3: Memory (U11.N8), MCU (U14.C12)
D4: Memory (U11.P9), MCU (U14.R8)
D5: Memory (U11.M8), MCU (U14.N9)
D6: Memory (U11.M7), MCU (U14.P9)
D7: Memory (U11.L8), MCU (U14.R9)
D8: Memory (U11.L2), MCU (U14.P10)
D9: Memory (U11.M3), MCU (U14.R10)
D10: Memory (U11.M2), MCU (U14.R12)
D11: Memory (U11.P1), MCU (U14.P11)
D12: Memory (U11.N2), MCU (U14.R11)
D13: Memory (U11.R1), MCU (U14.L15)
D14: Memory (U11.N3), MCU (U14.L14)
D15: Memory (U11.R2), MCU (U14.K15)
D16: Memory (U11.E8), MCU (U14.P14)
D17: Memory (U11.D7), MCU (U14.N14)
D18: Memory (U11.D8), MCU (U14.P15)
D19: Memory (U11.B9), MCU (U14.N15)
D20: Memory (U11.C8), MCU (U14.M15)
D21: Memory (U11.A9), MCU (U14.E12)
D22: Memory (U11.C7), MCU (U14.E13)
D23: Memory (U11.A8), MCU (U14.D13)
D24: Memory (U11.A2), MCU (U14.E14)
D25: Memory (U11.C3), MCU (U14.D14)
D26: Memory (U11.A1), MCU (U14.C14)
D27: Memory (U11.C2), MCU (U14.C13)
D28: Memory (U11.B1), MCU (U14.D6)
D29: Memory (U11.D2), MCU (U14.D4)
D30: Memory (U11.D3), MCU (U14.E4)
D31: Memory (U11.E2), MCU (U14.D5)
HSSI_CLK_N: MCU (U14.H13), DSI_LCD (CN10.12)
HSSI_CLK_P: MCU (U14.H12), DSI_LCD (CN10.14)
HSSI_D0_N: MCU (U14.J13), DSI_LCD (CN10.8)
HSSI_D0_P: MCU (U14.J12), DSI_LCD (CN10.10)
HSSI_D1_N: MCU (U14.F13), DSI_LCD (CN10.16)
HSSI_D1_P: MCU (U14.F12), DSI_LCD (CN10.18)
I2C1_SCL: Peripherals (CN11.3), MCU (R140.2 U14.A7), Arduino_ Connectors (CN5.10 SB11.1), DSI_LCD (CN2.3)
I2C1_SDA: Peripherals (CN11.1), MCU (R142.2 U14.B4), Arduino_ Connectors (CN5.9 SB9.1), DSI_LCD (CN2.4)
I2C2_SCL: MCU (R121.2 U14.H4), AUDIO2 (U5.2)
I2C2_SDA: MCU (R124.2 U14.J3), AUDIO2 (U5.1)
LCD_BL_CTRL: MCU (U14.R2), DSI_LCD (R119.2)
LCD_INT: MCU (U14.M14), DSI_LCD (CN2.2 R36.2)
LCD_RST: MCU (U14.N13), DSI_LCD (CN2.5 CN10.5 R34.2)
MIC_CK: MCU (R87.1), AUDIO2 (U1.3 U2.3 U6.3)
NRST: Peripherals (SB1.1), ST_LINK_V2-1 (SB2.2), MCU (U14.J1), Arduino_ Connectors (CN6.3), ExtensionConnector (CN12.4)
PA0: Peripherals (R18.2), MCU (U14.N3)
PA1: MCU (U14.N2), Arduino_ Connectors (CN7.4)
PA2: MCU (U14.P2), Arduino_ Connectors (CN7.6)
PA4: MCU (U14.N4), Arduino_ Connectors (SB12.1)
PA5: MCU (U14.P4), ExtensionConnector (CN12.7)
PA6: MCU (U14.P3), Arduino_ Connectors (CN7.7)
PA7: MCU (U14.R3), Arduino_ Connectors (CN5.2)
PA8: MCU (U14.F15), ExtensionConnector (CN12.3)
PA10: MCU (U14.D15), USB_OTG_FS (R161.2)
PA13: ST_LINK_V2-1 (R20.2 U3.27), MCU (U14.A15)
PA14: ST_LINK_V2-1 (U3.15 U3.26), MCU (U14.A14)
PA15: MCU (U14.A13), ExtensionConnector (CN12.11)
PB0: Peripherals (CN11.4), MCU (U14.R5)
PB1: MCU (U14.R4), Arduino_ Connectors (CN8.1)
PB2: MCU (U14.M5), USB_OTG_FS (R151.2)
PB4: MCU (U14.A9), ExtensionConnector (CN12.5)
PB5: MCU (U14.A8), ExtensionConnector (CN12.9)
PB6: MCU (U14.B6), QSPI (R55.1 U12.1)
PB7: MCU (U14.B5), USB_OTG_FS (R156.1)
PB10: ST_LINK_V2-1 (U3.13), MCU (U14.P12)
PB11: ST_LINK_V2-1 (U3.12), MCU (U14.R13)
PB12: MCU (U14.L13), ExtensionConnector (CN12.12)
PB13: MCU (U14.K14), ExtensionConnector (CN12.10)
PB14: MCU (U14.R14), Arduino_ Connectors (CN5.5)
PB15: MCU (U14.R15), Arduino_ Connectors (CN5.4)
PC0: Memory (TP2.1 U11.K8), MCU (U14.M2)
PC1: MCU (U14.M3), ExtensionConnector (CN12.14)
PC2: MCU (U14.M4), Arduino_ Connectors (CN8.2)
PC3: MCU (U14.L4), Arduino_ Connectors (CN8.3)
PC4: MCU (U14.N5), Arduino_ Connectors (CN8.4)
PC5: MCU (U14.P5), Arduino_ Connectors (SB10.1)
PC6: MCU (U14.H15), ExtensionConnector (CN12.6)
PC7: MCU (U14.G15), ExtensionConnector (CN12.8)
PC8: Peripherals (CN9.7 R114.2), MCU (U14.G14)
PC10: Peripherals (CN9.1 R120.2), MCU (U14.B14)
PC11: Peripherals (CN9.2 R116.2), MCU (U14.B13)
PC12: Peripherals (CN9.5), MCU (U14.A12)
PC13: MCU (U14.D1), ExtensionConnector (CN12.13)
PD2: Peripherals (CN9.3 R115.2), MCU (U14.D12)
PD3: MCU (U14.C11), Arduino_ Connectors (CN5.6 SB5.2)
PD4: Peripherals (R3.1), MCU (U14.D11)
PD5: Peripherals (R4.1), MCU (U14.C10)
PD6: MCU (U14.B11), AUDIO2 (SB17.2 SB18.2 U2.4)
PE0: Memory (U11.K9), MCU (U14.A6)
PE1: Memory (U11.K1), MCU (U14.A5)
PE3: MCU (U14.A2), AUDIO2 (R46.2)
PE4: MCU (U14.A1), AUDIO2 (U5.40)
PE5: MCU (U14.B1), AUDIO2 (U5.38)
PE6: MCU (U14.B2), AUDIO2 (U5.39)
PF6: MCU (U14.K2), QSPI (U12.7)
PF7: MCU (U14.K1), QSPI (U12.3)
PF8: MCU (U14.L3), QSPI (TP6.1 U12.5)
PF9: MCU (U14.L2), QSPI (TP7.1 U12.2)
PF10: MCU (U14.L1), QSPI (TP5.1 U12.6)
PF11: Memory (U11.J9), MCU (U14.P8)
PG2: Peripherals (R57.1), MCU (U14.M13)
PG6: Peripherals (R2.1), MCU (U14.J15)
PG7: MCU (U14.J14), AUDIO2 (U5.37)
PG8: Memory (TP3.1 U11.J1), MCU (U14.H14)
PG9: MCU (U14.D9), Arduino_ Connectors (CN7.1)
PG10: MCU (U14.C8), Arduino_ Connectors (CN5.1)
PG11: MCU (U14.B8), Arduino_ Connectors (CN7.8)
PG12: MCU (U14.C7), Arduino_ Connectors (CN7.5)
PG13: MCU (U14.B3), Arduino_ Connectors (CN7.3)
PG14: MCU (U14.A4), Arduino_ Connectors (CN7.2)
PG15: Memory (U11.K7), MCU (U14.B7)
PH2: Memory (U11.J2), MCU (U14.K4)
PH3: Memory (U11.J8), MCU (U14.J4)
PH6: MCU (U14.P13), Arduino_ Connectors (CN5.3)
PI4: Memory (U11.F8), MCU (U14.C3)
PI5: Memory (U11.F2), MCU (U14.D3)
PJ2: MCU (U14.P7), DSI_LCD (CN10.22)
PK3: Peripherals (R5.1), MCU (U14.D8)
SPKR_OUTAN: AUDIO2 (U5.6), ExtensionConnector (CN12.15)
SPKR_OUTAP: AUDIO2 (U5.4), ExtensionConnector (CN12.16)
STLK_MCO: ST_LINK_V2-1 (C26.1 R35.2), MCU (SB19.1)
SWO: ST_LINK_V2-1 (SB3.2), MCU (SB7.1)
USB_FS1_N: MCU (U14.C15), USB_OTG_FS (D5.D3 R160.2)
USB_FS1_P: MCU (U14.B15), USB_OTG_FS (D5.C3 R159.2)
uSD_D1: Peripherals (CN9.8 R86.2), MCU (R135.2)

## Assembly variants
F469NIH6: not fitted C4 C13 C26 CN4 R29 R31 R34 R43 R119 R144 R150 TP1 TP2 TP3 TP4 TP5 TP6 TP7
